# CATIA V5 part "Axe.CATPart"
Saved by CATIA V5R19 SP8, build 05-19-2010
Part number: Axe
Publications: "L", "r", "a"
Bounding box of the stored display mesh (mm): x -25 to 95, y -10 to 10, z -10 to 10
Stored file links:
  C:\Users\ThinkMotion\Desktop\EU_thinkMotion\iao\IAO_MMS_Groupe3\evulliez\evulliez\evulliez\Mecanisme\Axe.CATPart
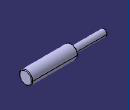
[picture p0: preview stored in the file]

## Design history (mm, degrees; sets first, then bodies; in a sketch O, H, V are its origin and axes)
Parameters
  L = 50 mm
  r = 5 mm
  LENGTH = 30 mm
  a = 70 mm
Body1 (main body)
  Point1: (0, 0, 0)
  Line1: type PtDir, RefPoint Point1, Direction (1, 0, 0), Start -25, End 25 {= L /2}
  Sketch1 on yz-plane, origin (0, 0, 0), H (0, 1, 0), V (0, 0, 1)
    circle A1 centre (0, 0) radius 5
    point P1 (0, 0)
    reference projected point E1 (0, 0) from Point1
    radius A1 = 5 {= r}
    coincidence: E1 P1
  Pad1: profile Sketch1, direction (1, 0, 0), length 25 {= L /2}, mirrored extent
  Sketch2 on end face of Pad1, origin (25, 0, 0), H (0, 1, 0), V (0, 0, 1)
    circle A1 centre (0, 0) radius 10
    point P1 (0, 0)
    reference projected point E1 (0, 0) from Point1
    radius A1 = 10 {= r +5mm}
    coincidence: P1 E1
  Pad2: profile Sketch2, direction (1, 0, 0), length 70 {= a}
  Fillet1: radius 1, on edge [start face of Pad1 | face of Pad1 from Sketch1.A1]; edge [start face of Pad2 | face of Pad2 from Sketch2.A1]; edge [face of Pad2 from Sketch2.A1 | end face of Pad2]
